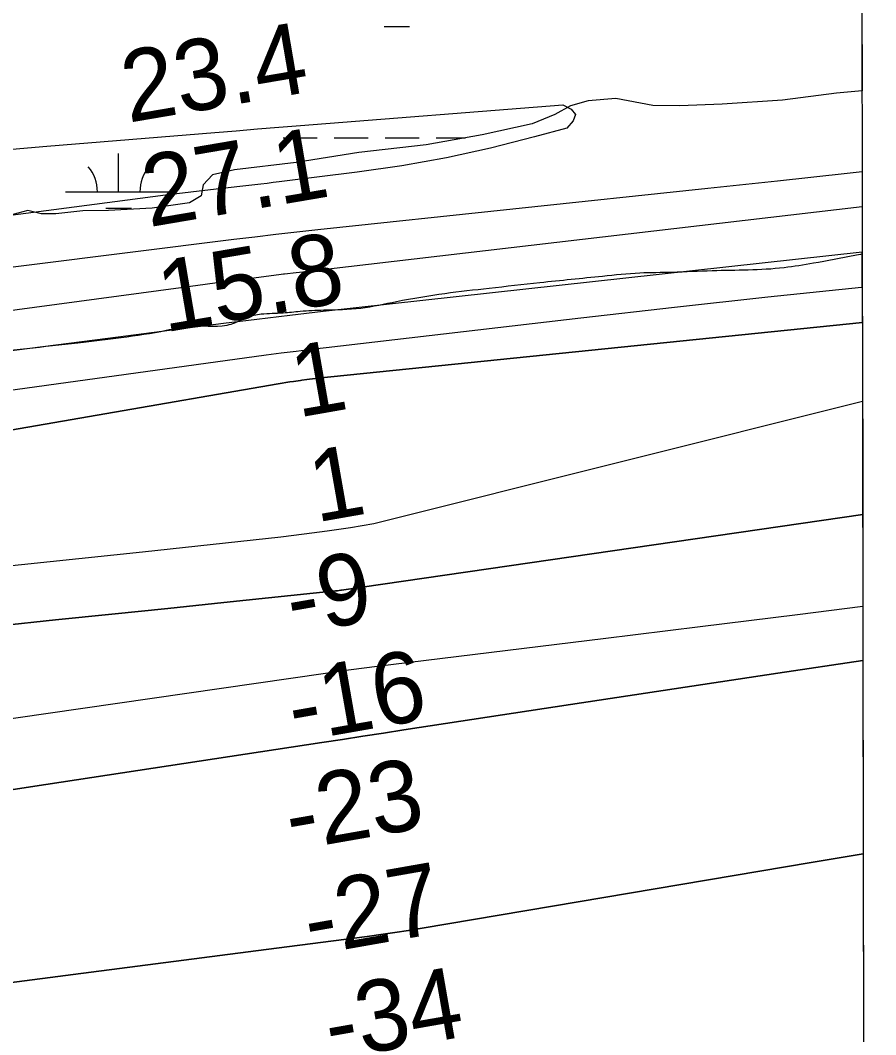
# Model space of a CAD drawing. Extents: x 3297772 to 3335630, y 634068 to 659439.
# Drawn here: x 3332648 to 3333452, y 647396 to 648350 of the extents above; entities that cross this region are included whole.
import ezdxf

# ---------------------------------------------------------------- set-up
doc = ezdxf.new("R2010")
doc.units = 0
for name, color, linetype in [('V-GRID-FRAM', 7, 'Continuous'), ('V-RIVR-EDGE', 7, 'Continuous'), ('V-RIVR-RANG', 7, 'Continuous'), ('V-SITE-VEGE', 7, 'Continuous'), ('V-TOPO-DPTH', 7, 'Continuous'), ('V-TOPO-MAJR', 7, 'Continuous'), ('V-TOPO-MINR', 7, 'Continuous'), ('V-TOPO-WATR', 7, 'Continuous'), ('V-WETL-SWMP', 7, 'Continuous')]:
    doc.layers.add(name, color=color, linetype=linetype)

msp = doc.modelspace()

# ---------------------------------------------------------------- linework, layer by layer
at = {"layer": 'V-GRID-FRAM'}
msp.add_lwpolyline([(3301870.22, 657630.6), (3333425.54, 657662.73), (3333451.99, 639478.67), (3301880.8, 639446.53), (3301870.22, 657630.6)], dxfattribs=at)
at = {"layer": 'V-RIVR-EDGE'}
msp.add_spline([(3333439.4, 648130.07), (3333432.26, 648128.6), (3333393.46, 648121.33), (3333365.91, 648117.13), (3333332.17, 648114.89), (3333298.43, 648114.2), (3333260.81, 648112.74), (3333230.17, 648112.04), (3333195.26, 648109.02), (3333136.3, 648102.97), (3333088.59, 648097.65), (3333047.08, 648092.71), (3333001.69, 648085.07), (3332967.93, 648078.95), (3332933.41, 648077.1), (3332910.92, 648075.99), (3332895.01, 648074.48), (3332874.46, 648073.36), (3332860.88, 648070.3), (3332849.23, 648064.89), (3332842.24, 648062.97), (3332806.95, 648061.9), (3332785.23, 648058.07), (3332742.94, 648051.2), (3332702.21, 648046.26), (3332606, 648034.47), (3332570.7, 648028.35), (3332514.83, 648018.8), (3332458.57, 648008.85), (3332396.12, 648000.48), (3332317.75, 647987.87), (3332285.55, 647982.52), (3332246.36, 647976.42), (3332207.96, 647971.86), (3332152.88, 647965.79), (3332088.49, 647961.29), (3332048.92, 647954.8), (3332019.05, 647950.22), (3331983.35, 647943.33), (3331945.33, 647935.66), (3331898, 647927.64), (3331843.29, 647918.08), (3331788.98, 647907.74), (3331738.16, 647900.5), (3331714.11, 647898.62), (3331693.93, 647894.02), (3331644.66, 647886.77), (3331609.35, 647880.26), (3331580.26, 647876.07), (3331563.2, 647876.11), (3331548.07, 647876.54), (3331538.38, 647876.17), (3331524.8, 647873.88), (3331503.46, 647868.5), (3331463.88, 647860.46), (3331402.97, 647851.3), (3331393.27, 647846.67), (3331382.01, 647841.27), (3331348.64, 647836.31), (3331302.48, 647830.22), (3331254.77, 647825.68), (3331162.07, 647821.65), (3331119.02, 647820.59), (3331084.5, 647817.19), (3331048.03, 647811.07), (3330992.95, 647804.62), (3330947.56, 647800.07), (3330916.92, 647796.66), (3330882.01, 647795.19), (3330846.71, 647791.4), (3330781.94, 647785.75), (3330745.08, 647780.02), (3330721.81, 647780.08), (3330687.31, 647783.65), (3330659, 647784.89), (3330629.53, 647784.57), (3330565.14, 647780.08), (3330512.78, 647775.17), (3330464.29, 647771.41), (3330411.15, 647764.95), (3330328.91, 647756.62), (3330280.81, 647752.47), (3330223.01, 647743.69), (3330159.77, 647733.77), (3330098.87, 647726.16), (3330018.57, 647717.05), (3329963.87, 647709.43), (3329917.71, 647702.95), (3329903.36, 647702.21), (3329890.56, 647702.25), (3329873.51, 647706.94), (3329862.26, 647707.75), (3329851.79, 647705.83), (3329827.73, 647698.91), (3329814.54, 647697.39), (3329809.49, 647696.63), (3329807.95, 647698.57), (3329806.79, 647701.68), (3329801.75, 647702.08), (3329782.75, 647701.35), (3329745.51, 647698.73), (3329718.75, 647695.69), (3329678.02, 647692.69), (3329648.15, 647688.88), (3329601.98, 647682.02), (3329556.21, 647675.93), (3329520.91, 647674.46), (3329508.12, 647675.27), (3329497.27, 647678.4), (3329465.46, 647674.6), (3329435.21, 647672.74), (3329406.12, 647671.26), (3329386.73, 647673.24), (3329372.01, 647678.71), (3329360.77, 647680.68), (3329347.58, 647681.48), (3329329.36, 647681.14), (3329318.87, 647676.51), (3329309.95, 647675.37), (3329285.52, 647674.66), (3329264.18, 647671.22), (3329230.05, 647668.98), (3329205.62, 647670.98), (3329192.82, 647669.46), (3329173.82, 647668.34), (3329159.86, 647669.54), (3329154.82, 647672.65), (3329142.02, 647669.97), (3329119.52, 647667.31), (3329104.39, 647666.19), (3329092.37, 647665.05), (3329070.26, 647665.11), (3329052.42, 647664.38), (3329042.73, 647664.79), (3329037.31, 647667.13), (3329035.38, 647670.62), (3329031.12, 647672.96), (3329023.36, 647673.37), (3329005.91, 647675.35), (3328975.68, 647679.3), (3328944.66, 647682.09), (3328895.41, 647682.6), (3328867.5, 647686.55), (3328838.8, 647688.56), (3328809.34, 647690.18), (3328773.66, 647691.82), (3328729.06, 647689.61), (3328666.24, 647693.64), (3328624.75, 647694.91), (3328580.16, 647695.79), (3328546.8, 647693.55), (3328506.84, 647687.05), (3328492.87, 647683.21), (3328482.77, 647675.09), (3328471.9, 647673.18), (3328434.28, 647669.78), (3328399.37, 647666.77), (3328372.6, 647660.63), (3328345.83, 647656.43), (3328313.24, 647653.41), (3328276.01, 647651.56), (3328220.15, 647646.27), (3328210.45, 647641.64), (3328198.03, 647638.18), (3328173.59, 647636.69), (3328112.7, 647631.8), (3328044.04, 647626.54), (3328041.33, 647628.48), (3328031.68, 647644.02), (3328021.23, 647654.52), (3328011.16, 647660.36), (3327997.99, 647665.82), (3327984.43, 647668.96), (3327951.08, 647672.14), (3327903.39, 647674.97), (3327857.25, 647678.58), (3327817.69, 647677.9), (3327782.79, 647676.43), (3327750.6, 647676.13), (3327707.94, 647675.46), (3327667.61, 647675.56), (3327640.47, 647680.28), (3327623.8, 647683.03), (3327599.38, 647684.26), (3327563.3, 647682.02), (3327529.17, 647680.16), (3327489.22, 647675.22), (3327442.66, 647667.58), (3327414.73, 647665.71), (3327389.53, 647666.16), (3327373.63, 647665.42), (3327367.43, 647667.38), (3327351.54, 647674.4), (3327334.11, 647680.26), (3327331.79, 647683.75), (3327330.25, 647688.8), (3327320.56, 647691.93), (3327317.47, 647695.81), (3327317.87, 647700.85), (3327315.16, 647702.8), (3327303.15, 647707.09), (3327298.5, 647707.49), (3327292.29, 647704.79), (3327281.81, 647701.72), (3327271.72, 647701.74), (3327235.27, 647702.22), (3327199.21, 647703.47), (3327168.96, 647704.32), (3327108.86, 647708.35), (3327072.81, 647712.7), (3327031.71, 647717.46), (3326986.73, 647719.9), (3326955.32, 647719.2), (3326928.95, 647718.1), (3326908, 647716.21), (3326887.82, 647708.12), (3326876.17, 647702.72), (3326868.8, 647701.96), (3326856.78, 647704.71), (3326842.05, 647704.74), (3326809.47, 647703.27), (3326777.27, 647698.31), (3326760.2, 647695.64), (3326748.94, 647691.4), (3326738.08, 647689.49), (3326737.31, 647691.04), (3326736.93, 647694.92), (3326734.61, 647696.86), (3326712.9, 647700.41), (3326678.39, 647702.05), (3326660.16, 647703.64), (3326628.38, 647711.48), (3326607.84, 647715.41), (3326582.63, 647714.3), (3326557.02, 647710.1), (3326535.69, 647708.99), (3326505.83, 647710.23), (3326475.98, 647711.85), (3326436.81, 647712.73), (3326394.54, 647711.67), (3326361.58, 647711.75), (3326334.82, 647714.14), (3326302.66, 647722.75), (3326245.3, 647737.63), (3326217.01, 647746.62), (3326194.53, 647752.11), (3326171.27, 647755.65), (3326147.62, 647755.32), (3326132.09, 647751.1), (3326110.74, 647743), (3326100.26, 647739.15), (3326091.73, 647738.79), (3326082.82, 647741.52), (3326084.38, 647746.17), (3326084.39, 647749.66), (3326081.3, 647753.16), (3326059.58, 647751.28), (3326025.83, 647748.26), (3325980.44, 647741), (3325936.6, 647735.29)], degree=3, dxfattribs=at)
at = {"layer": 'V-SITE-VEGE'}
for p, q in [((3333437.62, 649358.92), (3333439.18, 648283.56)), ((3333439.18, 648283.56), (3333415.02, 648281.1)), ((3333181.69, 648274.02), (3333165.05, 648269.39)), ((3333207.62, 648276.31), (3333181.69, 648274.02)), ((3333242.44, 648269.69), (3333207.62, 648276.31)), ((3333364.32, 648274.58), (3333307.83, 648270.78)), ((3333415.02, 648281.1), (3333364.32, 648274.58)), ((3333165.05, 648269.39), (3333150.33, 648261.29)), ((3333267.97, 648269.27), (3333242.44, 648269.69)), ((3333307.83, 648270.78), (3333267.97, 648269.27)), ((3333150.33, 648261.29), (3333129.04, 648252.41)), ((3333129.04, 648252.41), (3333082.21, 648242.02)), ((3333082.21, 648242.02), (3333029.58, 648232.79)), ((3332966.11, 648225.52), (3332907.29, 648215.91)), ((3333029.58, 648232.79), (3332966.11, 648225.52)), ((3332907.29, 648215.91), (3332849.24, 648209.01)), ((3332849.24, 648209.01), (3332828.73, 648204.39)), ((3332828.73, 648204.39), (3332819.82, 648195.12)), ((3332819.82, 648195.12), (3332817.87, 648184.67)), ((3332807.03, 648178.11), (3332771.82, 648173.12)), ((3332817.87, 648184.67), (3332807.03, 648178.11)), ((3332654.96, 648170.93), (3332641.03, 648167.08)), ((3332667.73, 648167.82), (3332654.96, 648170.93)), ((3332706.81, 648170.49), (3332681.27, 648167.81)), ((3332730.8, 648170.84), (3332706.81, 648170.49)), ((3332771.82, 648173.12), (3332730.8, 648170.84)), ((3332681.27, 648167.81), (3332667.73, 648167.82))]:
    msp.add_line(p, q, dxfattribs=at)
at = {"layer": 'V-TOPO-DPTH'}
for points in [[(3333439.5, 648065.66), (3333439.4, 648131.67), (3332963.75, 648079.47), (3332932.55, 648075.96), (3332901.36, 648072.33), (3332870.18, 648068.54), (3332839.02, 648064.64), (3332730.16, 648050.7), (3332644.59, 648039.62), (3332559.05, 648028.39), (3332473.53, 648016.91), (3332388.04, 648005.27), (3332202.14, 647979.71), (3332173.03, 647975.71), (3332143.93, 647971.72), (3332114.82, 647967.73), (3332085.71, 647963.76), (3331617.84, 647899.97)], [(3333439.5, 648065.66), (3333439.76, 647885.02), (3332950.03, 647813.99), (3332949.4, 647813.9), (3332946.07, 647813.48), (3332944.52, 647813.31), (3332944.17, 647813.28), (3332839.41, 647802.42), (3332786.68, 647796.95), (3332733.96, 647791.48), (3332681.23, 647786.02), (3332628.5, 647780.55), (3332191.86, 647735.29), (3332190.98, 647735.2), (3332187.01, 647734.77), (3332186.13, 647734.66), (3332170.27, 647732.69), (3332162.12, 647731.66), (3332153.98, 647730.63), (3332145.83, 647729.59), (3332137.68, 647728.53), (3331350.13, 647626.05)], [(3331805.9, 647834.86), (3332110.41, 647875.2), (3332135.24, 647878.64), (3332160.03, 647882.27), (3332184.78, 647886.2), (3332209.5, 647890.32), (3332890.47, 648007.99), (3332894.04, 648008.59), (3332897.62, 648009.18), (3332901.19, 648009.75), (3332904.77, 648010.3), (3332911.29, 648011.28), (3332912.59, 648011.46), (3332917.21, 648012), (3332919.85, 648012.31), (3332922.49, 648012.6), (3332925.13, 648012.89), (3332927.77, 648013.17), (3333439.5, 648065.66)], [(3331805.9, 647834.86), (3332110.41, 647875.2), (3332135.24, 647878.64), (3332160.03, 647882.27), (3332184.78, 647886.2), (3332209.5, 647890.32), (3332890.47, 648007.99), (3332894.04, 648008.59), (3332897.62, 648009.18), (3332901.19, 648009.75), (3332904.77, 648010.3), (3332911.29, 648011.28), (3332912.59, 648011.46), (3332917.21, 648012), (3332919.85, 648012.31), (3332922.49, 648012.6), (3332925.13, 648012.89), (3332927.77, 648013.17), (3333439.5, 648065.66)], [(3331350.13, 647626.05), (3332137.68, 647728.53), (3332145.83, 647729.59), (3332153.98, 647730.63), (3332162.12, 647731.66), (3332170.27, 647732.69), (3332186.13, 647734.66), (3332187.01, 647734.77), (3332190.98, 647735.2), (3332191.86, 647735.29), (3332628.5, 647780.55), (3332681.23, 647786.02), (3332733.96, 647791.48), (3332786.68, 647796.95), (3332839.41, 647802.42), (3332944.17, 647813.28), (3332944.52, 647813.31), (3332946.07, 647813.48), (3332949.4, 647813.9), (3332950.03, 647813.99), (3333439.76, 647885.02), (3333439.96, 647747.98)], [(3333439.96, 647747.98), (3333359.99, 647736.08), (3333262.5, 647721.38), (3333165.03, 647706.56), (3333008.49, 647682.62), (3332989.22, 647679.67), (3332969.95, 647676.73), (3332950.68, 647673.79), (3332931.41, 647670.84), (3332657.51, 647629.05), (3332584.17, 647617.99), (3332510.8, 647607.09), (3332437.4, 647596.43), (3332363.97, 647585.94), (3332288.16, 647575.24), (3332252.61, 647570.27), (3332217.05, 647565.37), (3332181.48, 647560.57), (3332145.9, 647555.84), (3331527.2, 647474.4)], [(3331527.2, 647474.4), (3332145.9, 647555.84), (3332181.48, 647560.57), (3332217.05, 647565.37), (3332252.61, 647570.27), (3332288.16, 647575.24), (3332363.97, 647585.94), (3332437.4, 647596.43), (3332510.8, 647607.09), (3332584.17, 647617.99), (3332657.51, 647629.05), (3332931.41, 647670.84), (3332950.68, 647673.79), (3332969.95, 647676.73), (3332989.22, 647679.67), (3333008.49, 647682.62), (3333165.03, 647706.56), (3333262.5, 647721.38), (3333359.99, 647736.08), (3333439.96, 647747.98), (3333440.22, 647566.18)], [(3333440.22, 647566.18), (3333391.3, 647557.93), (3333025.8, 647496.31), (3333012.89, 647494.21), (3332999.96, 647492.22), (3332987.01, 647490.37), (3332974.05, 647488.62), (3332879.13, 647476.39), (3332818.69, 647468.59), (3332758.26, 647460.76), (3332697.83, 647452.89), (3332637.41, 647445.01), (3332300.37, 647400.9), (3332273.44, 647397.16), (3332246.56, 647393.14)], [(3332246.56, 647393.14), (3332273.44, 647397.16), (3332300.37, 647400.9), (3332637.41, 647445.01), (3332697.83, 647452.89), (3332758.26, 647460.76), (3332818.69, 647468.59), (3332879.13, 647476.39), (3332974.05, 647488.62), (3332987.01, 647490.37), (3332999.96, 647492.22), (3333012.89, 647494.21), (3333025.8, 647496.31), (3333391.3, 647557.93), (3333440.22, 647566.18), (3333440.47, 647395.26)]]:
    msp.add_lwpolyline(points, dxfattribs=at)
at = {"layer": 'V-TOPO-MAJR'}
for points in [[(3331830.3, 648100.37), (3332064.04, 648161.09), (3332086.01, 648166.31), (3332108.09, 648170.91), (3332130.35, 648174.6), (3332152.72, 648177.67), (3332295.94, 648194.29), (3332390.05, 648204.72), (3332484.23, 648214.5), (3332578.51, 648223.3), (3332672.85, 648231.46), (3332830.79, 648244.29), (3332850.9, 648245.92), (3332871.01, 648247.54), (3332891.12, 648249.16), (3332911.23, 648250.76), (3333157.8, 648270.4), (3333165.74, 648266.15), (3333169.7, 648261.2)], [(3333169.7, 648261.2), (3333167.68, 648255.19), (3333161.67, 648248.47), (3333131.27, 648240.05), (3333090, 648229.59), (3333048.49, 648220.36), (3333006.62, 648212.98), (3332964.49, 648206.83), (3332891.38, 648197.8), (3332885.63, 648197.1), (3332879.88, 648196.4), (3332874.12, 648195.73), (3332868.36, 648195.06), (3332832.17, 648190.9), (3332808.32, 648188.1), (3332784.49, 648185.23), (3332760.66, 648182.24), (3332736.85, 648179.18), (3332150.88, 648102.32)]]:
    msp.add_lwpolyline(points, dxfattribs=at)
at = {"layer": 'V-TOPO-MINR'}
for points in [[(3333439.29, 648207.4), (3333425.11, 648205.8), (3333359.73, 648198.61), (3333294.33, 648191.57), (3332927.75, 648152.67), (3332907.97, 648150.52), (3332888.2, 648148.29), (3332868.44, 648145.95), (3332848.69, 648143.53), (3332456.19, 648094.36), (3332401.74, 648087.41), (3332347.31, 648080.3), (3332292.91, 648072.92), (3332238.54, 648065.38), (3332150.47, 648052.96), (3332140.15, 648051.49), (3332129.83, 648050.01), (3332119.52, 648048.49), (3332109.21, 648046.96), (3331704.39, 647986.34)], [(3333439.34, 648174.29), (3332932.31, 648115.22), (3332926.04, 648114.49), (3332919.77, 648113.76), (3332913.5, 648113.04), (3332907.23, 648112.32), (3332896.32, 648111.06), (3332895.5, 648110.97), (3332893.06, 648110.66), (3332862.76, 648106.71), (3332846.8, 648104.62), (3332830.84, 648102.51), (3332814.88, 648100.39), (3332798.93, 648098.25), (3332215.8, 648019.78), (3332176.49, 648014.47), (3332137.19, 648009.13), (3332097.89, 648003.76), (3332058.59, 647998.35), (3332022.76, 647993.41), (3331965.56, 647985.51), (3331908.35, 647977.61), (3331851.15, 647969.7), (3331793.94, 647961.79)], [(3333439.4, 648131.67), (3332963.75, 648079.47), (3332932.55, 648075.96), (3332901.36, 648072.33), (3332870.18, 648068.54), (3332839.02, 648064.64), (3332730.16, 648050.7), (3332644.59, 648039.62), (3332559.05, 648028.39), (3332473.53, 648016.91), (3332388.04, 648005.27), (3332202.14, 647979.71), (3332173.03, 647975.71), (3332143.93, 647971.72), (3332114.82, 647967.73), (3332085.71, 647963.76), (3331617.84, 647899.97)], [(3333439.45, 648098.61), (3333438.59, 648098.53), (3333350.65, 648089.44), (3333262.77, 648079.82), (3333174.92, 648069.86), (3332935.36, 648041.94), (3332921.29, 648040.26), (3332907.23, 648038.51), (3332893.17, 648036.68), (3332879.13, 648034.79), (3332202.68, 647941.68)], [(3333439.6, 647991.28), (3332980.13, 647876.35), (3332958.37, 647872.75), (3332936.57, 647869.43), (3332914.7, 647866.54), (3332892.8, 647863.93), (3332762.95, 647849.74), (3332676.06, 647840.54), (3332589.13, 647831.75), (3332502.15, 647823.55), (3332415.12, 647815.75), (3332237.29, 647800.43), (3332206.5, 647797.73), (3332175.71, 647794.98), (3332144.94, 647792.14), (3332114.16, 647789.25), (3332031.11, 647781.32), (3331958.81, 647774.4), (3331886.52, 647767.47), (3331814.22, 647760.53)], [(3333439.76, 647885.02), (3332950.03, 647813.99), (3332949.4, 647813.9), (3332946.07, 647813.48), (3332944.52, 647813.31), (3332944.17, 647813.28), (3332839.41, 647802.42), (3332786.68, 647796.95), (3332733.96, 647791.48), (3332681.23, 647786.02), (3332628.5, 647780.55), (3332191.86, 647735.29), (3332190.98, 647735.2), (3332187.01, 647734.77), (3332186.13, 647734.66), (3332170.27, 647732.69), (3332162.12, 647731.66), (3332153.98, 647730.63), (3332145.83, 647729.59), (3332137.68, 647728.53), (3331350.13, 647626.05)], [(3333439.88, 647798.78), (3333378.47, 647790.95), (3333287.11, 647779.53), (3333195.73, 647768.24), (3332983.42, 647742.25), (3332971.27, 647740.72), (3332959.12, 647739.14), (3332946.99, 647737.48), (3332934.86, 647735.77), (3332415.43, 647660.71)], [(3333439.96, 647747.98), (3333359.99, 647736.08), (3333262.5, 647721.38), (3333165.03, 647706.56), (3333008.49, 647682.62), (3332989.22, 647679.67), (3332969.95, 647676.73), (3332950.68, 647673.79), (3332931.41, 647670.84), (3332657.51, 647629.05), (3332584.17, 647617.99), (3332510.8, 647607.09), (3332437.4, 647596.43), (3332363.97, 647585.94), (3332288.16, 647575.24), (3332252.61, 647570.27), (3332217.05, 647565.37), (3332181.48, 647560.57), (3332145.9, 647555.84), (3331527.2, 647474.4)], [(3333440.22, 647566.18), (3333391.3, 647557.93), (3333025.8, 647496.31), (3333012.89, 647494.21), (3332999.96, 647492.22), (3332987.01, 647490.37), (3332974.05, 647488.62), (3332879.13, 647476.39), (3332818.69, 647468.59), (3332758.26, 647460.76), (3332697.83, 647452.89), (3332637.41, 647445.01), (3332300.37, 647400.9), (3332273.44, 647397.16), (3332246.56, 647393.14)]]:
    msp.add_lwpolyline(points, dxfattribs=at)
at = {"layer": 'V-TOPO-WATR'}
msp.add_lwpolyline([(3333439.5, 648065.66), (3332927.77, 648013.17), (3332925.13, 648012.89), (3332922.49, 648012.6), (3332919.85, 648012.31), (3332917.21, 648012), (3332912.59, 648011.46), (3332911.29, 648011.28), (3332904.77, 648010.3), (3332901.19, 648009.75), (3332897.62, 648009.18), (3332894.04, 648008.59), (3332890.47, 648007.99), (3332209.5, 647890.32), (3332184.78, 647886.2), (3332160.03, 647882.27), (3332135.24, 647878.64), (3332110.41, 647875.2), (3331805.9, 647834.86)], dxfattribs=at)
at = {"layer": 'V-WETL-SWMP'}
for p, q in [((3333437.52, 649425.06), (3333439.18, 648283.56)), ((3332989.87, 648343.91), (3333013.87, 648343.91)), ((3333439.18, 648283.56), (3333415.02, 648281.1)), ((3333181.69, 648274.02), (3333165.05, 648269.39)), ((3333207.62, 648276.31), (3333181.69, 648274.02)), ((3333242.43, 648269.69), (3333207.62, 648276.31)), ((3333364.32, 648274.58), (3333307.83, 648270.78)), ((3333415.02, 648281.1), (3333364.32, 648274.58)), ((3333165.05, 648269.39), (3333150.34, 648261.29)), ((3333267.97, 648269.27), (3333242.43, 648269.69)), ((3333307.83, 648270.78), (3333267.97, 648269.27)), ((3333150.34, 648261.29), (3333129.04, 648252.41)), ((3333129.04, 648252.41), (3333082.21, 648242.02)), ((3332895.02, 648239.27), (3332927.02, 648239.27)), ((3332943.02, 648239.27), (3332975.02, 648239.27)), ((3332991.02, 648239.27), (3333023.02, 648239.27)), ((3333082.21, 648242.02), (3333029.58, 648232.79)), ((3333039.02, 648239.27), (3333066.52, 648239.27)), ((3332966.12, 648225.52), (3332907.29, 648215.91)), ((3333029.58, 648232.79), (3332966.12, 648225.52)), ((3332740.43, 648188.53), (3332740.43, 648224.53)), ((3332907.29, 648215.91), (3332849.24, 648209.01)), ((3332849.24, 648209.01), (3332828.73, 648204.39)), ((3332828.73, 648204.39), (3332819.82, 648195.12)), ((3332690.43, 648188.53), (3332790.43, 648188.53)), ((3332819.82, 648195.12), (3332817.87, 648184.67)), ((3332807.03, 648178.11), (3332771.82, 648173.12)), ((3332817.87, 648184.67), (3332807.03, 648178.11)), ((3332654.96, 648170.93), (3332641.03, 648167.08)), ((3332667.73, 648167.82), (3332654.96, 648170.93)), ((3332706.81, 648170.49), (3332681.27, 648167.81)), ((3332730.8, 648170.84), (3332706.81, 648170.49)), ((3332728.43, 648173.09), (3332752.43, 648173.09)), ((3332771.82, 648173.12), (3332730.8, 648170.84)), ((3332681.27, 648167.81), (3332667.73, 648167.82))]:
    msp.add_line(p, q, dxfattribs=at)
for centre, start, end in [((3332685.19, 648189), 359.22818, 40.77184), ((3332795.67, 648189), 139.22818, 180.77184)]:
    msp.add_arc(centre, 35.25, start, end, dxfattribs=at)

# ---------------------------------------------------------------- texts
at = {"layer": 'V-RIVR-RANG'}
for s, rotation, p in [('23.4', 9.68833, (3332749.45, 648253.33)), ('27.1', 9.68833, (3332768.86, 648155.2)), ('15.8', 9.68833, (3332783.6, 648056.27)), ('1', 9.97564, (3332909.02, 647976.19)), ('1', 9.97564, (3332926.1, 647877.66)), ('-9', 9.97564, (3332903.69, 647772.18)), ('-16', 9.97564, (3332905.45, 647670.95)), ('-23', 9.97564, (3332902.78, 647568.95)), ('-27', 9.97564, (3332920.38, 647470.51)), ('-34', 9.97564, (3332939.8, 647372.39))]:
    msp.add_text(s, height=67, rotation=rotation, dxfattribs=at).set_placement(p)

doc.saveas('drawing.dxf')
